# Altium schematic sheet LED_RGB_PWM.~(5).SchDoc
size A4
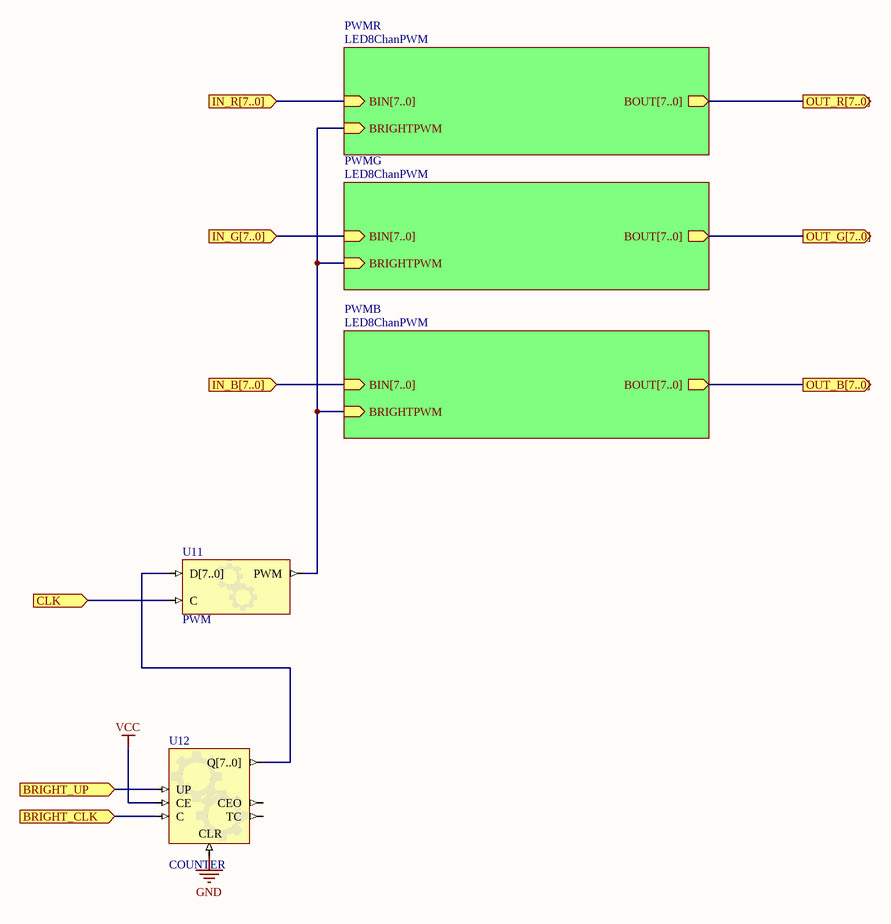
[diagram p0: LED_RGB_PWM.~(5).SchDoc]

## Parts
U11  PWM
U12  COUNTER

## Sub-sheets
PWMB = LED8ChanPWM: BIN[7..0] (in), BOUT[7..0] (out), BRIGHTPWM (in)
PWMG = LED8ChanPWM: BIN[7..0] (in), BOUT[7..0] (out), BRIGHTPWM (in)
PWMR = LED8ChanPWM: BIN[7..0] (in), BOUT[7..0] (out), BRIGHTPWM (in)

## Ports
BRIGHT_CLK (in), BRIGHT_UP (in), CLK (in), IN_B[7..0] (in), IN_G[7..0] (in), IN_R[7..0] (in), OUT_B[7..0] (out), OUT_G[7..0] (out), OUT_R[7..0] (out)

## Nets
GND: U12.CLR
VCC: U12.CE
BRIGHT_CLK: U12.C ; port BRIGHT_CLK
BRIGHT_UP: U12.UP ; port BRIGHT_UP
CLK: U11.C ; port CLK
NetU11_PWM: U11.PWM ; sheet PWMR/BRIGHTPWM, sheet PWMG/BRIGHTPWM, sheet PWMB/BRIGHTPWM

Not connected (* = marked no-connect by the designer): U11 D[7..0]; U12 CEO Q[7..0] TC

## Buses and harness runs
bus port IN_B[7..0] = sheet PWMB/BIN[7..0]
bus port IN_G[7..0] = sheet PWMG/BIN[7..0]
bus port IN_R[7..0] = sheet PWMR/BIN[7..0]
bus port OUT_B[7..0] = sheet PWMB/BOUT[7..0]
bus port OUT_G[7..0] = sheet PWMG/BOUT[7..0]
bus port OUT_R[7..0] = sheet PWMR/BOUT[7..0]

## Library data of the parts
U11 = PWM: Configurable PWM; ConfiguratorName: GENERIC_PWM; ConfigurationParameters: {}Version[1.0]{}Width[8]{}Prescaler[1]{}
U12 = COUNTER: Configurable Counter; ConfiguratorName: GENERIC_COUNTER; ConfigurationParameters: {}Version[1.0]{}Type[Binary]{}SyncReset[False]{}NegativeClockEdge[False]{}FixedDirection[False]{}IsIncrement[False]{}SignalWidth[8]{}MaxValue[255]{}BusOutput[True]{}Loadable[False]{}BusInput[False]{}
